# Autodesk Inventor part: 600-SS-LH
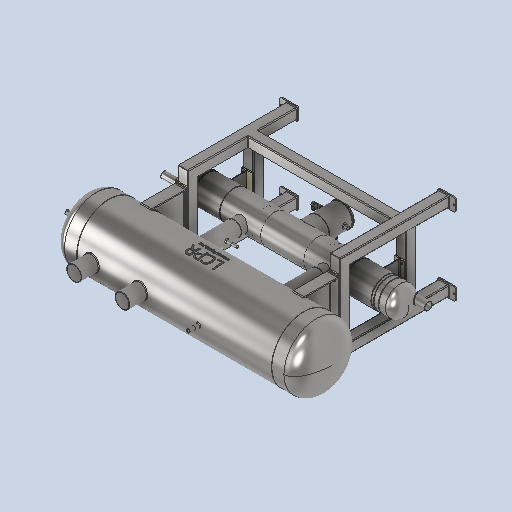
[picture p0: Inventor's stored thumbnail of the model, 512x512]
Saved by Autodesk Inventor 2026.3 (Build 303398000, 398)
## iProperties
Created: 2026-05
Part Number: 600-SS-LH
Material: Generic
Document SubType Name: Modeling
Designer: rva
Density: 1 g/cm^3
Appearance: Default
Author: rva
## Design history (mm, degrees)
derived "LCPR-SS-600-FULL-ASSEMBLY-LH.iam"
body "Solid1"
node "LCPR-SS-600-FULL FRAME ASSEMBLY.iam:1::LCPR-SS-600-FRAME ASS"
node "LCPR-SS-600-1840-125-WELD.iam:1::600 mm Dome End Cap.ipt:1"
node "LCPR-SS-600-1840-125-WELD.iam:1::600 mm Dome End Cap.ipt:2"
node "LCPR-SS-600-1840-125-WELD.iam:1::LPR-600-Leg Assembly.iam:1:"
node "LCPR-SS-600-1840-125-WELD.iam:1::LPR-600-Leg Assembly.iam:2:"
node "LCPR-SS-600-1840-125-WELD.iam:1::H1100-R.ipt:1"
node "LCPR-SS-600-1840-125-WELD.iam:1::LCPR-LOGO.ipt:1"
node "LCPR-SS-600-1840-125-WELD.iam:1::Welds"
node "Sub-SS-250-125-1712-52-10-65-50-LH.iam:1::SS-250-52 hole Sub"
node "Sub-SS-250-125-1712-52-10-65-50-LH.iam:1::SS-250-52 hole Sub"
node "Sub-SS-250-125-1712-52-10-65-50-LH.iam:1::SS-250 mm Subcoole"
node "Sub-SS-250-125-1712-52-10-65-50-LH.iam:1::SS-250 mm Subcoole"
node "Sub-SS-250-125-1712-52-10-65-50-LH.iam:1::H1100-R.ipt:2"
node "Sub-SS-250-125-1712-52-10-65-50-LH.iam:1::Welds"
node "Sub-SS-250-125-1712-52-10-65-50-LH.iam:1::1-2 Inch NPT Socke"
node "Sub-SS-250-125-1712-52-10-65-50-LH.iam:1::200 mm Oil Pot Ass"
node "AS 1111 - Metric M10 x 130:2"
node "AS 1111 - Metric M10 x 130:1"
node "AS 1111 - Metric M10 x 130:4"
node "AS 1111 - Metric M10 x 130:3"
node "AS 1111 - Metric M12 x 140:2"
node "AS 1111 - Metric M12 x 140:1"
node "AS 1111 - Metric M10 x 140:1"
node "AS 1111 - Metric M10 x 140:2"
node "AS 1112 (4) - Metric M12:1"
node "AS 1112 (4) - Metric M12:4"
node "AS 1112 (4) - Metric M12:3"
node "AS 1112 (4) - Metric M10:4"
node "AS 1112 (4) - Metric M10:3"
node "AS 1112 (4) - Metric M10:1"
node "AS 1112 (4) - Metric M10:2"
node "AS 1237 (4.1) 10 mm:9"
node "AS 1237 (4.1) 10 mm:6"
node "AS 1237 (4.1) 10 mm:7"
node "AS 1237 (4.1) 10 mm:8"
node "AS 1237 (4.1) 10 mm:10"
node "AS 1237 (4.1) 10 mm:4"
node "AS 1237 (4.1) 10 mm:5"
node "AS 1237 (4.1) 10 mm:11"
node "AS 1237 (4.1) 12 mm:1"
node "AS 1237 (4.1) 10 mm:2"
node "AS 1237 (4.1) 10 mm:3"
node "AS 1237 (4.1) 12 mm:2"
node "AS 1237 (4.1) 12 mm:5"
node "AS 1237 (4.1) 12 mm:4"
node "AS 1237 (4.1) 12 mm:6"
node "AS 1237 (4.1) 12 mm:3"
node "Nylon Heat Tranfer Spacer 568x100.ipt:1"
node "Nylon Heat Tranfer Spacer 568x100.ipt:2"
node "Nylon Heat Tranfer Spacer 175x100.ipt:1"
node "Nylon Heat Tranfer Spacer 175x100.ipt:2"
node "AS 1112 (4) - Metric M12:2"
node "Welds"
node "LCPR-SS-600-FULL-ASSEMBLY-LH.iam_Bodies"
